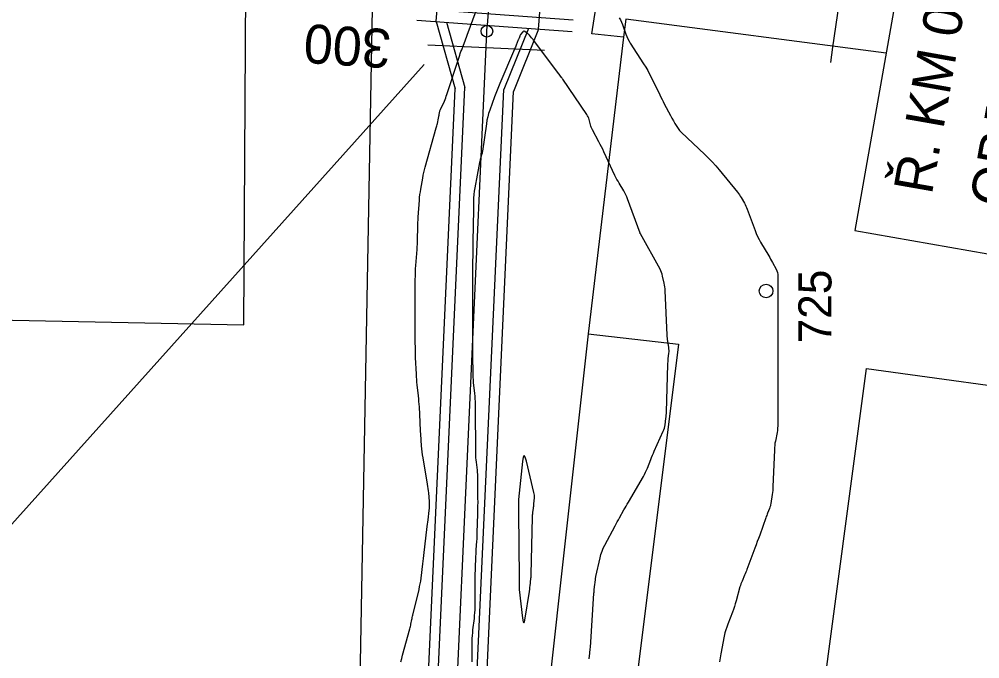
# Model space of a CAD drawing. Extents: x -534481 to -534256, y -1190577 to -1190138.
# Drawn here: x -534356.7 to -534332.03, y -1190280.77 to -1190264.34 of the extents above; entities that cross this region are included whole.
import ezdxf

# ---------------------------------------------------------------- set-up
doc = ezdxf.new("R2010")
doc.units = 0
for name, color, linetype in [('0_kroužky', 7, 'Continuous'), ('30', 7, 'Continuous'), ('31', 7, 'Continuous'), ('_N_osa', 7, 'Continuous'), ('_N_tenká', 7, 'Continuous'), ('_N_text', 7, 'Continuous'), ('_tenka', 7, 'Continuous'), ('_tenká_čárkovaná', 7, 'Continuous'), ('Hranice parcel', 7, 'Continuous'), ('Parcelní čísla', 7, 'Continuous'), ('Polygon budovy', 7, 'Continuous'), ('Vrstva 1', 7, 'Continuous'), ('Značky budov', 7, 'Continuous')]:
    doc.layers.add(name, color=color, linetype=linetype)

msp = doc.modelspace()

# ---------------------------------------------------------------- linework, layer by layer
at = {"layer": '0_kroužky'}
msp.add_circle((-534344.689, -1190264.646), 0.15, dxfattribs=at)
msp.add_circle((-534344.689, -1190264.646), 0.15, dxfattribs=at)
msp.add_circle((-534344.689, -1190264.646), 0.15, dxfattribs=at)
msp.add_circle((-534344.689, -1190264.646), 0.15, dxfattribs=at)
msp.add_circle((-534344.689, -1190264.646), 0.15, dxfattribs=at)
msp.add_circle((-534344.689, -1190264.646), 0.15, dxfattribs=at)
at = {"layer": '30'}
for points in [[(-534346.896, -1190280.845), (-534346.875, -1190280.759), (-534346.852, -1190280.673), (-534346.665, -1190279.996), (-534346.657, -1190279.967), (-534346.65, -1190279.938), (-534346.644, -1190279.909), (-534346.638, -1190279.88), (-534346.616, -1190279.764), (-534346.61, -1190279.735), (-534346.604, -1190279.706), (-534346.597, -1190279.677), (-534346.591, -1190279.648), (-534346.431, -1190278.987), (-534346.415, -1190278.916), (-534346.401, -1190278.844), (-534346.389, -1190278.771), (-534346.379, -1190278.699), (-534346.335, -1190278.334), (-534346.317, -1190278.189), (-534346.309, -1190278.116), (-534346.219, -1190277.371), (-534346.197, -1190277.196), (-534346.168, -1190276.956), (-534346.163, -1190276.9), (-534346.161, -1190276.844), (-534346.161, -1190276.788), (-534346.164, -1190276.732), (-534346.183, -1190276.508), (-534346.188, -1190276.452), (-534346.195, -1190276.396), (-534346.202, -1190276.34), (-534346.211, -1190276.284), (-534346.328, -1190275.606), (-534346.34, -1190275.53), (-534346.35, -1190275.455), (-534346.358, -1190275.379), (-534346.364, -1190275.302), (-534346.385, -1190274.997), (-534346.39, -1190274.921), (-534346.395, -1190274.844), (-534346.399, -1190274.768), (-534346.403, -1190274.692), (-534346.423, -1190274.299), (-534346.427, -1190274.228), (-534346.433, -1190274.157), (-534346.439, -1190274.087), (-534346.446, -1190274.016), (-534346.477, -1190273.735), (-534346.484, -1190273.664), (-534346.49, -1190273.594), (-534346.495, -1190273.523), (-534346.499, -1190273.453), (-534346.518, -1190273.032), (-534346.522, -1190272.938), (-534346.524, -1190272.844), (-534346.526, -1190272.751), (-534346.527, -1190272.657), (-534346.527, -1190271.027), (-534346.526, -1190270.936), (-534346.523, -1190270.845), (-534346.519, -1190270.754), (-534346.512, -1190270.663), (-534346.481, -1190270.256), (-534346.476, -1190270.187), (-534346.472, -1190270.118), (-534346.469, -1190270.048), (-534346.468, -1190269.979), (-534346.463, -1190269.701), (-534346.461, -1190269.631), (-534346.459, -1190269.562), (-534346.455, -1190269.493), (-534346.451, -1190269.423), (-534346.421, -1190268.988), (-534346.415, -1190268.916), (-534346.407, -1190268.845), (-534346.397, -1190268.774), (-534346.386, -1190268.703), (-534346.336, -1190268.419), (-534346.322, -1190268.348), (-534346.307, -1190268.278), (-534346.29, -1190268.208), (-534346.272, -1190268.138), (-534345.987, -1190267.129), (-534345.98, -1190267.101), (-534345.973, -1190267.073), (-534345.966, -1190267.044), (-534345.96, -1190267.016), (-534345.932, -1190266.883), (-534345.928, -1190266.864), (-534345.924, -1190266.844), (-534345.92, -1190266.825), (-534345.917, -1190266.806), (-534345.903, -1190266.729), (-534345.899, -1190266.71), (-534345.894, -1190266.692), (-534345.888, -1190266.674), (-534345.88, -1190266.656), (-534345.781, -1190266.441), (-534345.763, -1190266.399), (-534345.746, -1190266.357), (-534345.73, -1190266.314), (-534345.715, -1190266.27), (-534345.403, -1190265.31), (-534345.387, -1190265.263), (-534345.371, -1190265.216), (-534345.354, -1190265.169), (-534345.336, -1190265.123), (-534345.262, -1190264.937), (-534345.243, -1190264.891), (-534345.226, -1190264.844), (-534345.208, -1190264.797), (-534345.191, -1190264.751), (-534344.965, -1190264.118)], [(-534341.295, -1190264.303), (-534341.26, -1190264.357), (-534341.23, -1190264.414), (-534341.206, -1190264.474), (-534341.119, -1190264.721), (-534341.096, -1190264.782), (-534341.069, -1190264.841), (-534341.038, -1190264.899), (-534341.005, -1190264.954), (-534340.665, -1190265.481), (-534340.61, -1190265.568), (-534340.558, -1190265.657), (-534340.509, -1190265.748), (-534340.463, -1190265.84), (-534340.247, -1190266.282), (-534340.219, -1190266.339), (-534340.19, -1190266.396), (-534340.161, -1190266.452), (-534340.132, -1190266.508), (-534339.971, -1190266.81), (-534339.962, -1190266.827), (-534339.953, -1190266.845), (-534339.944, -1190266.862), (-534339.935, -1190266.879), (-534339.9, -1190266.949), (-534339.891, -1190266.966), (-534339.881, -1190266.983), (-534339.871, -1190267), (-534339.861, -1190267.016), (-534339.778, -1190267.145), (-534339.76, -1190267.171), (-534339.74, -1190267.196), (-534339.719, -1190267.22), (-534339.697, -1190267.243), (-534339.095, -1190267.81), (-534338.998, -1190267.905), (-534338.903, -1190268.004), (-534338.811, -1190268.105), (-534338.723, -1190268.209), (-534338.256, -1190268.779), (-534338.23, -1190268.812), (-534338.205, -1190268.847), (-534338.182, -1190268.882), (-534338.161, -1190268.918), (-534338.077, -1190269.064), (-534338.057, -1190269.101), (-534338.039, -1190269.139), (-534338.022, -1190269.177), (-534338.006, -1190269.216), (-534337.802, -1190269.763), (-534337.771, -1190269.842), (-534337.736, -1190269.918), (-534337.699, -1190269.993), (-534337.658, -1190270.067), (-534337.451, -1190270.419), (-534337.426, -1190270.461), (-534337.402, -1190270.503), (-534337.379, -1190270.546), (-534337.355, -1190270.588), (-534337.263, -1190270.759), (-534337.243, -1190270.803), (-534337.228, -1190270.847), (-534337.22, -1190270.894), (-534337.217, -1190270.942), (-534337.217, -1190274.732), (-534337.218, -1190274.788), (-534337.222, -1190274.844), (-534337.229, -1190274.9), (-534337.238, -1190274.955), (-534337.28, -1190275.176), (-534337.29, -1190275.231), (-534337.297, -1190275.286), (-534337.303, -1190275.342), (-534337.306, -1190275.398), (-534337.343, -1190276.348), (-534337.345, -1190276.398), (-534337.349, -1190276.448), (-534337.355, -1190276.497), (-534337.361, -1190276.547), (-534337.396, -1190276.78), (-534337.402, -1190276.812), (-534337.409, -1190276.843), (-534337.419, -1190276.874), (-534337.43, -1190276.905), (-534337.479, -1190277.025), (-534337.491, -1190277.055), (-534337.502, -1190277.085), (-534337.514, -1190277.115), (-534337.525, -1190277.146), (-534337.683, -1190277.591), (-534337.713, -1190277.675), (-534337.744, -1190277.76), (-534337.775, -1190277.844), (-534337.806, -1190277.928), (-534338.011, -1190278.473), (-534338.025, -1190278.511), (-534338.04, -1190278.548), (-534338.056, -1190278.585), (-534338.072, -1190278.623), (-534338.137, -1190278.771), (-534338.152, -1190278.808), (-534338.166, -1190278.845), (-534338.179, -1190278.884), (-534338.191, -1190278.922), (-534338.289, -1190279.284), (-534338.31, -1190279.357), (-534338.333, -1190279.43), (-534338.358, -1190279.501), (-534338.384, -1190279.573), (-534338.503, -1190279.878), (-534338.53, -1190279.953), (-534338.554, -1190280.029), (-534338.574, -1190280.106), (-534338.591, -1190280.184), (-534338.682, -1190280.64), (-534338.7, -1190280.743), (-534338.713, -1190280.846)]]:
    msp.add_lwpolyline(points, dxfattribs=at)
msp.add_lwpolyline([(-534343.574, -1190278.864), (-534343.572, -1190278.845), (-534343.568, -1190278.806), (-534343.556, -1190278.7), (-534343.554, -1190278.676), (-534343.552, -1190278.652), (-534343.55, -1190278.628), (-534343.55, -1190278.604), (-534343.518, -1190277.128), (-534343.517, -1190277.1), (-534343.515, -1190277.071), (-534343.512, -1190277.043), (-534343.509, -1190277.014), (-534343.493, -1190276.901), (-534343.49, -1190276.873), (-534343.486, -1190276.844), (-534343.484, -1190276.816), (-534343.481, -1190276.787), (-534343.469, -1190276.635), (-534343.468, -1190276.6), (-534343.469, -1190276.566), (-534343.474, -1190276.531), (-534343.48, -1190276.497), (-534343.673, -1190275.693), (-534343.706, -1190275.585), (-534343.733, -1190275.55), (-534343.756, -1190275.588), (-534343.774, -1190275.7), (-534343.873, -1190276.677), (-534343.875, -1190276.694), (-534343.876, -1190276.711), (-534343.877, -1190276.727), (-534343.877, -1190276.744), (-534343.876, -1190276.811), (-534343.876, -1190276.828), (-534343.876, -1190276.844), (-534343.877, -1190276.861), (-534343.877, -1190276.878), (-534343.879, -1190276.947), (-534343.879, -1190276.964), (-534343.879, -1190276.981), (-534343.879, -1190276.998), (-534343.879, -1190277.015), (-534343.858, -1190278.702), (-534343.857, -1190278.716), (-534343.858, -1190278.73), (-534343.858, -1190278.745), (-534343.858, -1190278.759), (-534343.86, -1190278.816), (-534343.86, -1190278.83), (-534343.86, -1190278.845), (-534343.861, -1190278.859), (-534343.861, -1190278.873), (-534343.861, -1190278.933), (-534343.861, -1190278.947), (-534343.86, -1190278.962), (-534343.859, -1190278.977), (-534343.857, -1190278.991), (-534343.772, -1190279.726), (-534343.757, -1190279.818), (-534343.741, -1190279.848), (-534343.723, -1190279.818), (-534343.704, -1190279.727), (-534343.595, -1190279.037), (-534343.592, -1190279.018), (-534343.589, -1190278.999), (-534343.587, -1190278.98), (-534343.585, -1190278.96)], close=True, dxfattribs=at)
at = {"layer": '31'}
msp.add_lwpolyline([(-534342.062, -1190280.771), (-534342.045, -1190280.625), (-534342.041, -1190280.588), (-534342.037, -1190280.551), (-534342.034, -1190280.514), (-534342.031, -1190280.478), (-534341.938, -1190279.084), (-534341.936, -1190279.06), (-534341.934, -1190279.036), (-534341.932, -1190279.012), (-534341.93, -1190278.988), (-534341.916, -1190278.864), (-534341.91, -1190278.806), (-534341.901, -1190278.729), (-534341.899, -1190278.71), (-534341.896, -1190278.691), (-534341.892, -1190278.672), (-534341.888, -1190278.653), (-534341.782, -1190278.176), (-534341.76, -1190278.091), (-534341.732, -1190278.008), (-534341.699, -1190277.928), (-534341.66, -1190277.849), (-534341.394, -1190277.35), (-534341.367, -1190277.299), (-534341.339, -1190277.248), (-534341.311, -1190277.197), (-534341.283, -1190277.147), (-534341.169, -1190276.945), (-534341.14, -1190276.895), (-534341.111, -1190276.845), (-534341.082, -1190276.795), (-534341.053, -1190276.744), (-534340.667, -1190276.082), (-534340.638, -1190276.031), (-534340.612, -1190275.978), (-534340.587, -1190275.925), (-534340.565, -1190275.87), (-534340.481, -1190275.65), (-534340.459, -1190275.595), (-534340.437, -1190275.54), (-534340.414, -1190275.486), (-534340.39, -1190275.432), (-534340.158, -1190274.922), (-534340.142, -1190274.883), (-534340.129, -1190274.843), (-534340.119, -1190274.802), (-534340.112, -1190274.76), (-534340.09, -1190274.592), (-534340.085, -1190274.55), (-534340.081, -1190274.508), (-534340.079, -1190274.466), (-534340.077, -1190274.423), (-534340.039, -1190273.212), (-534340.038, -1190273.175), (-534340.035, -1190273.138), (-534340.033, -1190273.102), (-534340.029, -1190273.065), (-534340.013, -1190272.918), (-534340.01, -1190272.881), (-534340.01, -1190272.845), (-534340.012, -1190272.808), (-534340.017, -1190272.772), (-534340.043, -1190272.61), (-534340.049, -1190272.57), (-534340.054, -1190272.531), (-534340.057, -1190272.492), (-534340.06, -1190272.452), (-534340.109, -1190271.309), (-534340.112, -1190271.262), (-534340.117, -1190271.215), (-534340.125, -1190271.169), (-534340.134, -1190271.122), (-534340.175, -1190270.937), (-534340.186, -1190270.891), (-534340.201, -1190270.847), (-534340.22, -1190270.804), (-534340.241, -1190270.762), (-534340.747, -1190269.853), (-534340.749, -1190269.848), (-534340.752, -1190269.836), (-534340.753, -1190269.833), (-534341.074, -1190268.952), (-534341.095, -1190268.899), (-534341.118, -1190268.847), (-534341.144, -1190268.796), (-534341.173, -1190268.747), (-534341.292, -1190268.551), (-534341.321, -1190268.502), (-534341.349, -1190268.452), (-534341.375, -1190268.401), (-534341.4, -1190268.35), (-534341.683, -1190267.743), (-534341.714, -1190267.679), (-534341.745, -1190267.615), (-534341.777, -1190267.552), (-534341.811, -1190267.489), (-534341.98, -1190267.176), (-534341.996, -1190267.145), (-534342.009, -1190267.113), (-534342.021, -1190267.081), (-534342.03, -1190267.047), (-534342.064, -1190266.912), (-534342.073, -1190266.879), (-534342.086, -1190266.847), (-534342.101, -1190266.816), (-534342.119, -1190266.787), (-534342.738, -1190265.88), (-534342.746, -1190265.868), (-534342.754, -1190265.856), (-534342.763, -1190265.844), (-534342.772, -1190265.832), (-534342.816, -1190265.774), (-534342.834, -1190265.751), (-534342.843, -1190265.739), (-534343.491, -1190264.877), (-534343.503, -1190264.861), (-534343.516, -1190264.845), (-534343.528, -1190264.829), (-534343.541, -1190264.813), (-534343.595, -1190264.749), (-534343.607, -1190264.735), (-534343.621, -1190264.722), (-534343.635, -1190264.71), (-534343.65, -1190264.699), (-534343.712, -1190264.656), (-534343.727, -1190264.648), (-534343.741, -1190264.647), (-534343.755, -1190264.652), (-534343.767, -1190264.663), (-534343.822, -1190264.73), (-534343.829, -1190264.74), (-534343.836, -1190264.751), (-534343.842, -1190264.762), (-534343.846, -1190264.773), (-534343.863, -1190264.821), (-534343.868, -1190264.833), (-534343.872, -1190264.844), (-534343.877, -1190264.856), (-534343.881, -1190264.868), (-534343.936, -1190265.005), (-534343.947, -1190265.032), (-534343.957, -1190265.058), (-534343.969, -1190265.085), (-534343.98, -1190265.111), (-534344.358, -1190265.99), (-534344.393, -1190266.074), (-534344.427, -1190266.159), (-534344.46, -1190266.244), (-534344.491, -1190266.329), (-534344.614, -1190266.673), (-534344.643, -1190266.759), (-534344.667, -1190266.847), (-534344.687, -1190266.935), (-534344.702, -1190267.025), (-534344.804, -1190267.728), (-534344.808, -1190267.752), (-534344.812, -1190267.776), (-534344.818, -1190267.801), (-534344.825, -1190267.825), (-534344.852, -1190267.92), (-534344.859, -1190267.944), (-534344.865, -1190267.968), (-534344.871, -1190267.992), (-534344.875, -1190268.017), (-534344.998, -1190268.671), (-534345.012, -1190268.758), (-534345.023, -1190268.845), (-534345.029, -1190268.933), (-534345.032, -1190269.021), (-534345.036, -1190269.4), (-534345.037, -1190269.475), (-534345.038, -1190269.55), (-534345.039, -1190269.625), (-534345.041, -1190269.7), (-534345.047, -1190270.001), (-534345.048, -1190270.076), (-534345.05, -1190270.152), (-534345.051, -1190270.227), (-534345.052, -1190270.302), (-534345.056, -1190270.671), (-534345.056, -1190270.758), (-534345.057, -1190270.845), (-534345.057, -1190270.931), (-534345.057, -1190271.018), (-534345.057, -1190272.672), (-534345.057, -1190272.758), (-534345.057, -1190272.844), (-534345.057, -1190272.931), (-534345.056, -1190273.017), (-534345.053, -1190273.396), (-534345.052, -1190273.466), (-534345.048, -1190273.535), (-534345.043, -1190273.605), (-534345.037, -1190273.675), (-534345.006, -1190273.953), (-534344.999, -1190274.023), (-534344.994, -1190274.093), (-534344.991, -1190274.162), (-534344.99, -1190274.232), (-534344.987, -1190274.656), (-534344.987, -1190274.75), (-534344.986, -1190274.844), (-534344.985, -1190274.939), (-534344.984, -1190275.033), (-534344.98, -1190275.502), (-534344.979, -1190275.555), (-534344.977, -1190275.608), (-534344.973, -1190275.661), (-534344.967, -1190275.714), (-534344.942, -1190275.925), (-534344.937, -1190275.978), (-534344.933, -1190276.031), (-534344.93, -1190276.084), (-534344.929, -1190276.138), (-534344.926, -1190276.645), (-534344.925, -1190276.745), (-534344.926, -1190276.844), (-534344.927, -1190276.944), (-534344.93, -1190277.044), (-534344.943, -1190277.532), (-534344.945, -1190277.587), (-534344.947, -1190277.642), (-534344.95, -1190277.696), (-534344.954, -1190277.751), (-534344.969, -1190277.969), (-534344.973, -1190278.023), (-534344.976, -1190278.078), (-534344.978, -1190278.133), (-534344.98, -1190278.187), (-534344.994, -1190278.659), (-534344.996, -1190278.752), (-534344.998, -1190278.845), (-534344.999, -1190278.937), (-534345, -1190279.03), (-534345.001, -1190279.439), (-534345.002, -1190279.513), (-534345.005, -1190279.586), (-534345.011, -1190279.66), (-534345.019, -1190279.733), (-534345.054, -1190280.027), (-534345.062, -1190280.1), (-534345.068, -1190280.174), (-534345.071, -1190280.248), (-534345.073, -1190280.322), (-534345.074, -1190280.677), (-534345.073, -1190280.761), (-534345.072, -1190280.844)], dxfattribs=at)
at = {"layer": '_N_osa'}
for points in [[(-534344.677, -1190264.494), (-534342.94, -1190242.55)], [(-534409.868, -1190391.439), (-534405.947, -1190382.816), (-534400.873, -1190377.487), (-534393.696, -1190372.718), (-534384.927, -1190365.477), (-534382.631, -1190361.148), (-534355.894, -1190347.823), (-534351.738, -1190342.389), (-534351.577, -1190328.316), (-534347.204, -1190300.921), (-534345.553, -1190283.64), (-534344.682, -1190264.494)]]:
    msp.add_lwpolyline(points, dxfattribs=at)
at = {"layer": '_N_tenká'}
for p, q in [((-534345.991, -1190264.397), (-534345.507, -1190266.125)), ((-534345.726, -1190264.417), (-534345.255, -1190266.096)), ((-534343.624, -1190264.572), (-534344.256, -1190266.142)), ((-534343.362, -1190264.591), (-534344.008, -1190266.196))]:
    msp.add_line(p, q, dxfattribs=at)
for points in [[(-534409.916, -1190390.337), (-534406.368, -1190382.532), (-534401.196, -1190377.102), (-534393.995, -1190372.316), (-534385.322, -1190365.155), (-534382.997, -1190360.772), (-534356.221, -1190347.427), (-534352.236, -1190342.217), (-534352.076, -1190328.274), (-534347.7, -1190300.857), (-534346.052, -1190283.605), (-534345.255, -1190266.096)], [(-534409.879, -1190389.652), (-534406.578, -1190382.39), (-534401.358, -1190376.909), (-534394.144, -1190372.115), (-534385.52, -1190364.994), (-534383.181, -1190360.584), (-534356.384, -1190347.229), (-534352.485, -1190342.131), (-534352.326, -1190328.253), (-534347.948, -1190300.826), (-534346.301, -1190283.588), (-534345.507, -1190266.125)], [(-534409.363, -1190391.537), (-534405.527, -1190383.099), (-534400.549, -1190377.873), (-534393.398, -1190373.12), (-534384.532, -1190365.799), (-534382.264, -1190361.524), (-534355.568, -1190348.219), (-534351.24, -1190342.56), (-534351.077, -1190328.359), (-534346.708, -1190300.984), (-534345.054, -1190283.675), (-534344.256, -1190266.142)], [(-534409.111, -1190391.586), (-534405.317, -1190383.241), (-534400.388, -1190378.065), (-534393.249, -1190373.321), (-534384.335, -1190365.96), (-534382.081, -1190361.712), (-534355.404, -1190348.417), (-534350.991, -1190342.646), (-534350.828, -1190328.38), (-534346.46, -1190301.016), (-534344.805, -1190283.693), (-534344.008, -1190266.196)]]:
    msp.add_lwpolyline(points, dxfattribs=at)
at = {"layer": '_N_text'}
msp.add_lwpolyline([(-534329.865, -1190239.303), (-534335.236, -1190269.762), (-534330.848, -1190270.536), (-534325.477, -1190240.077)], close=True, dxfattribs=at)
for points in [[(-534343.21, -1190265.144), (-534346.207, -1190265.007)], [(-534409.732, -1190388.64), (-534397.101, -1190322.153), (-534346.296, -1190265.502)]]:
    msp.add_lwpolyline(points, dxfattribs=at)
at = {"layer": '_tenka'}
for p, q in [((-534346.465, -1190264.062), (-534342.476, -1190264.356)), ((-534346.487, -1190264.361), (-534342.498, -1190264.655))]:
    msp.add_line(p, q, dxfattribs=at)
at = {"layer": '_tenká_čárkovaná'}
for points in [[(-534345.991, -1190264.397), (-534344.257, -1190242.488)], [(-534343.362, -1190264.591), (-534341.628, -1190242.676)]]:
    msp.add_lwpolyline(points, dxfattribs=at)
at = {"layer": 'Hranice parcel'}
msp.add_line((-534348.02, -1190285.43), (-534347.63, -1190264.06), dxfattribs=at)
for points in [[(-534341.18, -1190264.8), (-534341.99, -1190264.71), (-534340.47, -1190254.93), (-534340.33, -1190252.09)], [(-534334.434, -1190265.214), (-534341.12, -1190264.34), (-534341.18, -1190264.8)], [(-534341.18, -1190264.8), (-534342.09, -1190272.42), (-534345.3, -1190301.34), (-534346.16, -1190306.72)]]:
    msp.add_lwpolyline(points, dxfattribs=at)
at = {"layer": 'Polygon budovy'}
msp.add_lwpolyline([(-534366.14, -1190271.54), (-534367.96, -1190291.63), (-534363.08, -1190291.98), (-534362.74, -1190289.52), (-534362.49, -1190289.56), (-534361.74, -1190280.34), (-534361.6, -1190280.35), (-534360.7, -1190271.99), (-534350.93, -1190272.19), (-534350.88, -1190263.57), (-534365.11, -1190263.3)], close=True, dxfattribs=at)
msp.add_lwpolyline([(-534334.434, -1190265.214), (-534341.12, -1190264.34), (-534341.18, -1190264.8), (-534342.09, -1190272.42), (-534339.77, -1190272.69), (-534343.2, -1190300.17), (-534333.12, -1190301.37), (-534332.25, -1190294.85), (-534337.72, -1190294.22), (-534334.94, -1190273.31), (-534329.83, -1190274.01), (-534329.03, -1190265.92), (-534330.011, -1190265.792)], dxfattribs=at)
at = {"layer": 'Vrstva 1'}
msp.add_lwpolyline([(-534335.852, -1190265.453), (-534335.802, -1190265.056), (-534335.43, -1190262.49), (-534334.79, -1190260.9)], dxfattribs=at)
at = {"layer": 'Značky budov'}
msp.add_circle((-534337.519, -1190271.32), 0.175, dxfattribs=at)

# ---------------------------------------------------------------- texts
at = {"layer": '_N_text'}
for s, rotation, p in [('OBJEM 9,7 m³ + PŘESPÁROVÁNÍ DLAŽBY', 80.0205, (-534331.31, -1190269.211)), ('Ř. KM 0,3225 - 0,330: TĚŽBA SEDIMENTU ', 80.0205, (-534333.264, -1190268.867)), ('300', 176.1676, (-534347.125, -1190264.605))]:
    msp.add_text(s, height=1, rotation=rotation, dxfattribs=at).set_placement(p)
at = {"layer": 'Parcelní čísla'}
msp.add_text('725', height=0.85, rotation=90, dxfattribs=at).set_placement((-534335.84, -1190272.667))

doc.saveas('drawing.dxf')
